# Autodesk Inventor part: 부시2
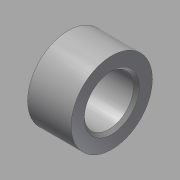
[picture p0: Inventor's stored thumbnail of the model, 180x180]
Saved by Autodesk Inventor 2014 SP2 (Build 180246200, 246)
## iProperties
Created: 2015-09
Part Number: 부시2
Material: 강철, 연강
Document SubType Name: Modeling
Designer: mduedu
Density: 7.86 g/cm^3
Description: 외주 가공
Mass: 45.4 g
Surface Area: 28.3815 cm^2
Volume: 5.77608 cm^3
Appearance: 강철
Author: mduedu
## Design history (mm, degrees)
sketch "스케치1"
  geometry: C1 r 14 at (0, 0); C2 r 8.5 at (0, 0); 1 further point
  constraints: 2 centre point, 2 coincident
  dimensions: "d0" = 28 diameter of C1; "d2" = 17 diameter of C2
extrude "돌출1" new body sketch "스케치1" distance "d3" = 15; taper "d4" = 0 deg
chamfer "모따기1" distance "d5" = 1; stored, may be unused: second distance "d6" = 2, angle "d7" = 45 deg
node "솔리드1"
